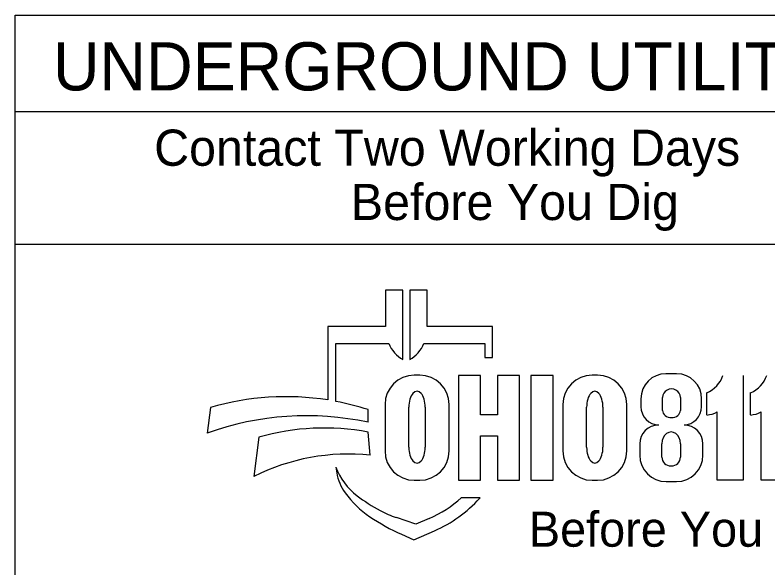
# Model space of a CAD drawing. Extents: x 0 to 72, y -85 to 22.
# Drawn here: x 42.946 to 46.068, y -9.844 to -7.552 of the extents above; entities that cross this region are included whole.
import ezdxf

# ---------------------------------------------------------------- set-up
doc = ezdxf.new("R2010")
doc.units = 0
doc.layers.add('GM_X_Township', color=7, linetype='Continuous')

msp = doc.modelspace()

# ---------------------------------------------------------------- linework, layer by layer
at = {"layer": 'GM_X_Township'}
for p, q in [((42.9464, -7.5516), (47.6964, -7.5516)), ((42.9464, -10.5516), (42.9464, -7.5516)), ((42.9464, -7.9516), (47.6964, -7.9516)), ((42.9464, -8.5016), (47.6964, -8.5016)), ((44.5545, -8.6921), (44.4817, -8.6921)), ((44.4817, -8.6921), (44.4817, -8.8435)), ((44.5545, -8.9801), (44.5545, -8.6921)), ((44.6556, -8.6921), (44.5828, -8.6921)), ((44.5828, -8.6921), (44.5828, -8.9801)), ((44.6556, -8.8435), (44.6556, -8.6921)), ((44.4817, -8.8435), (44.2427, -8.8435)), ((44.2427, -8.8435), (44.2427, -9.1475)), ((44.9262, -8.8435), (44.6556, -8.8435)), ((44.9262, -8.9709), (44.9262, -8.8435)), ((44.277, -9.1535), (44.277, -8.9133)), ((44.277, -8.9133), (44.4958, -8.9133)), ((44.6415, -8.9133), (44.8946, -8.9133)), ((44.8946, -8.9133), (44.8946, -8.9709)), ((44.8946, -8.9709), (44.9262, -8.9709)), ((44.6243, -9.0446), (44.6018, -9.0446)), ((44.8769, -9.0459), (44.7846, -9.0459)), ((44.7846, -9.0459), (44.7846, -9.4804)), ((45.3613, -9.0446), (45.3389, -9.0446)), ((45.6896, -9.0386), (45.6452, -9.0386)), ((45.9657, -9.0459), (45.9657, -9.4804)), ((45.5415, -9.1423), (45.5415, -9.1753)), ((45.6314, -9.1907), (45.6314, -9.1374)), ((45.7049, -9.1374), (45.7049, -9.1907)), ((45.7932, -9.1753), (45.7932, -9.1423)), ((45.8142, -9.2098), (45.8142, -9.1172)), ((45.9961, -9.2098), (45.9961, -9.1172)), ((44.4803, -9.1661), (44.4803, -9.3589)), ((44.5793, -9.3435), (44.5793, -9.1773)), ((44.6469, -9.1773), (44.6469, -9.3435)), ((44.7458, -9.3589), (44.7458, -9.1661)), ((45.2174, -9.1661), (45.2174, -9.3589)), ((45.3164, -9.3435), (45.3164, -9.1773)), ((45.384, -9.1773), (45.384, -9.3435)), ((45.4828, -9.3589), (45.4828, -9.1661)), ((43.7563, -9.1786), (43.7436, -9.2847)), ((44.4099, -9.2402), (44.4099, -9.1874)), ((45.858, -9.4804), (45.858, -9.1971)), ((46.04, -9.4804), (46.04, -9.1971)), ((43.9569, -9.3016), (43.9369, -9.4647)), ((44.4191, -9.377), (44.4106, -9.2806)), ((44.8769, -9.4804), (44.8769, -9.2967)), ((45.5365, -9.3299), (45.5365, -9.3761)), ((45.6281, -9.3842), (45.6281, -9.3287)), ((45.7054, -9.3287), (45.7054, -9.3842)), ((45.7987, -9.3761), (45.7987, -9.3299)), ((44.2761, -9.4258), (44.2803, -9.4501)), ((44.6018, -9.4804), (44.6243, -9.4804)), ((44.7846, -9.4804), (44.8769, -9.4804)), ((45.3389, -9.4804), (45.3613, -9.4804)), ((45.6464, -9.4861), (45.6888, -9.4861)), ((45.9657, -9.4804), (45.858, -9.4804)), ((46.1476, -9.4804), (46.04, -9.4804)), ((44.8747, -9.5532), (44.7967, -9.5532)), ((44.8725, -9.5556), (44.8747, -9.5532)), ((44.608, -9.663), (44.5273, -9.6352)), ((44.6637, -9.6388), (44.608, -9.663)), ((44.5491, -9.7045), (44.5998, -9.7268)), ((44.5998, -9.7268), (44.6857, -9.6895))]:
    msp.add_line(p, q, dxfattribs=at)
for points in [[(44.8769, -9.2967), (44.9461, -9.2967), (44.9461, -9.4804), (45.0384, -9.4804), (45.0384, -9.0459), (44.9461, -9.0459), (44.9461, -9.2098), (44.8769, -9.2098), (44.8769, -9.0459)], [(45.0846, -9.4804), (45.1779, -9.4804), (45.1779, -9.0459), (45.0846, -9.0459), (45.0846, -9.4804)], [(45.6151, -9.2513), (45.6151, -9.2513)], [(45.7201, -9.2513), (45.7201, -9.2513)]]:
    msp.add_lwpolyline(points, dxfattribs=at)
for centre, radius, start, end in [((44.6199, -8.8634), 0.1337, 201.9296, 240.7469), ((44.5175, -8.8634), 0.1337, 299.2531, 338.0704), ((44.6018, -9.1661), 0.1215, 90, 180), ((44.6243, -9.1661), 0.1215, 0, 90), ((45.3389, -9.1661), 0.1215, 90, 180), ((45.3613, -9.1661), 0.1215, 0, 90), ((45.6452, -9.1423), 0.1036, 90, 180), ((45.6896, -9.1423), 0.1036, 0, 90), ((45.7681, -9.0063), 0.1202, 292.5572, 340.7355), ((45.95, -9.0063), 0.1202, 292.5572, 340.7355), ((44.0688, -10.2461), 1.1123, 81.0007, 106.3144), ((44.0688, -10.2461), 1.1123, 72.1402, 79.2074), ((45.6176, -9.1753), 0.076, 180, 268.1442), ((45.7172, -9.1753), 0.076, 272.2058, 0), ((45.8033, -9.0902), 0.1202, 275.1733, 297.0931), ((45.9852, -9.0902), 0.1202, 275.1733, 297.0931), ((44.1544, -10.4242), 1.2113, 77.8238, 109.8274), ((44.2284, -10.2581), 0.9943, 79.44, 105.8467), ((45.6151, -9.3299), 0.0786, 90, 180), ((45.7201, -9.3299), 0.0786, 0, 90), ((44.6018, -9.3589), 0.1215, 180, 270), ((44.6243, -9.3589), 0.1215, 270, 0), ((45.3389, -9.3589), 0.1215, 180, 270), ((45.3613, -9.3589), 0.1215, 270, 0), ((44.3262, -10.2353), 0.8633, 83.8248, 116.8021), ((45.6464, -9.3761), 0.1099, 180, 270), ((45.6888, -9.3761), 0.1099, 270, 0), ((44.5306, -9.3279), 0.2727, 201.0457, 232.5314), ((44.4722, -9.4174), 0.1947, 189.6817, 216.0884), ((44.6537, -9.2851), 0.4193, 216.0884, 235.7167), ((44.7921, -8.9867), 0.7025, 232.5314, 241.794), ((44.4689, -9.19), 0.4892, 293.4582, 312.0712), ((44.4689, -9.19), 0.5445, 293.4582, 317.8286), ((44.6764, -9.2024), 0.4578, 241.794, 250.9821), ((44.8798, -8.9534), 0.8207, 235.7167, 246.2325)]:
    msp.add_arc(centre, radius, start, end, dxfattribs=at)
for centre, major_axis, ratio, start_param, end_param in [((44.6131, -9.1773), (0, 0.0657), 0.514403, 4.712389, 7.853982), ((45.3502, -9.1773), (0, 0.0657), 0.514403, 4.712389, 7.853982), ((45.6681, -9.1374), (0.0368, 0), 0.969373, 0, 3.141593), ((45.6681, -9.1907), (0.0368, 0), 0.818453, 3.141593, 6.283185), ((45.6668, -9.3287), (0, 0.0486), 0.794529, 4.712389, 7.853982), ((44.6131, -9.3435), (0, 0.0657), 0.514403, 1.570796, 4.712389), ((45.3502, -9.3435), (0, 0.0657), 0.514403, 1.570796, 4.712389), ((45.6668, -9.3842), (0.0386, 0), 0.959837, 3.141593, 6.283185)]:
    msp.add_ellipse(centre, major_axis=major_axis, ratio=ratio, start_param=start_param, end_param=end_param, dxfattribs=at)

# ---------------------------------------------------------------- texts
for s, height, p in [('UNDERGROUND UTILITIES', 0.2, (43.1033, -7.8642)), ('Contact Two Working Days', 0.15, (43.5231, -8.1765)), ('Before You Dig', 0.15, (44.3387, -8.4015)), ('Before You Dig', 0.1452, (45.0768, -9.7559))]:
    msp.add_text(s, height=height, dxfattribs=at).set_placement(p)

doc.saveas('drawing.dxf')
